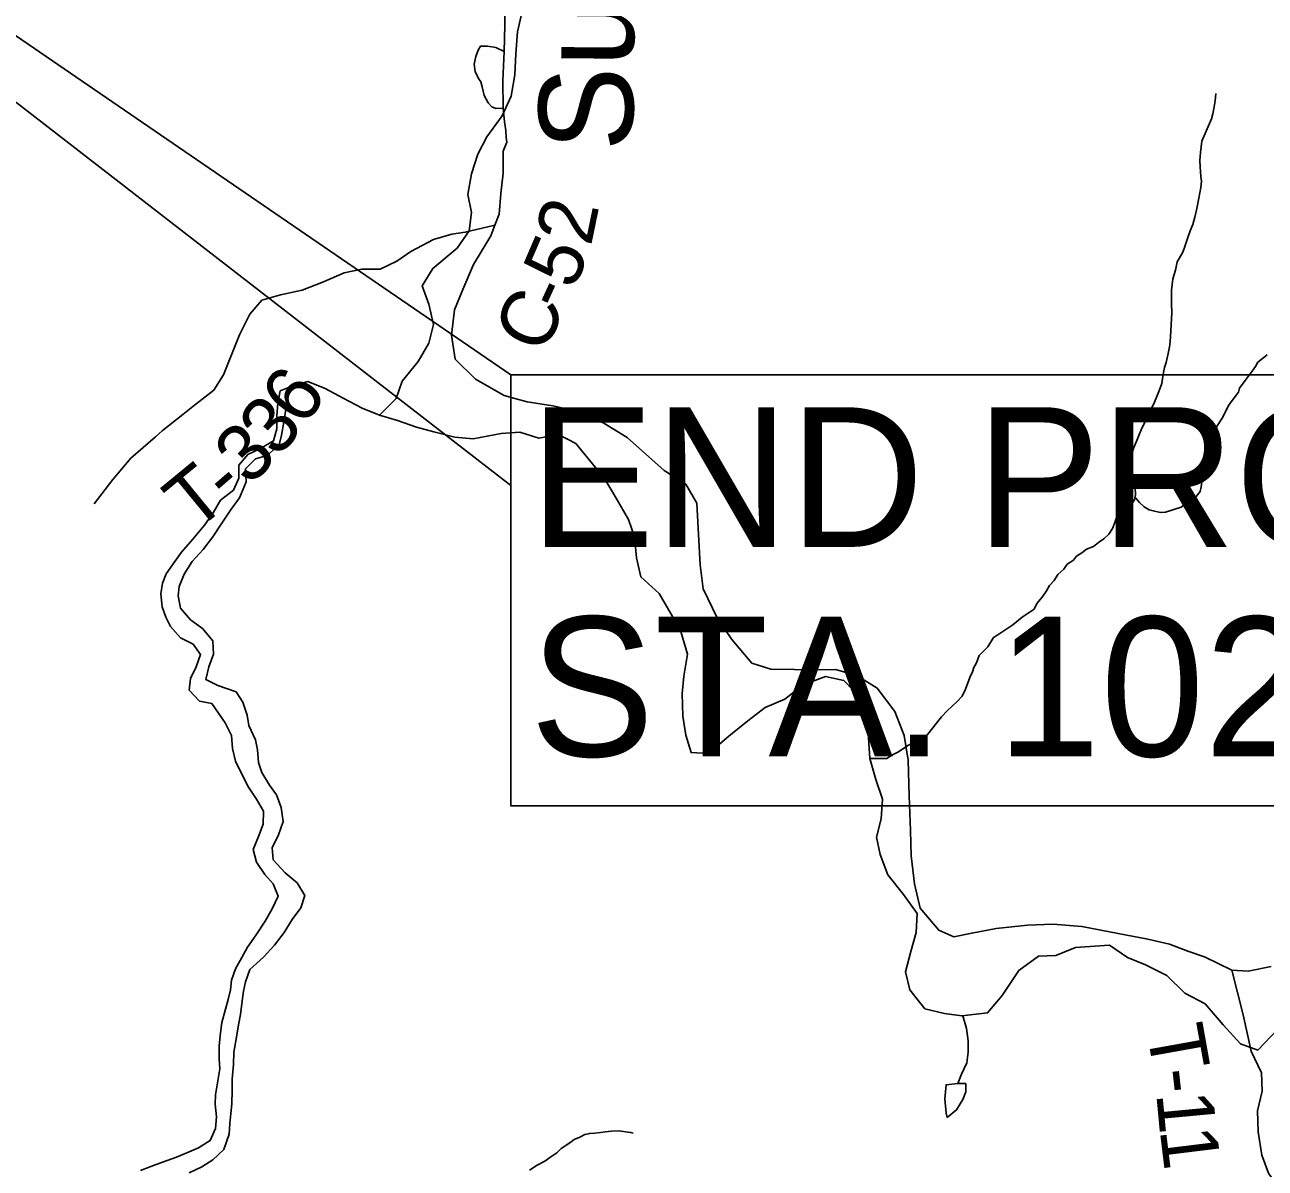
# Model space of a CAD drawing. Extents: x 0 to 34, y 0 to 22.
# Drawn here: x 5.45 to 6.694, y 15.248 to 16.395 of the extents above; entities that cross this region are included whole.
import ezdxf

# ---------------------------------------------------------------- set-up
doc = ezdxf.new("R2010")
doc.units = 0
for name, color, linetype in [('GM_X_County_Road', 7, 'Continuous'), ('GM_X_County_Road_Text', 7, 'Continuous'), ('GM_X_Major_River', 7, 'Continuous'), ('GM_X_Minor_Lake', 7, 'Continuous'), ('GM_X_Minor_River', 7, 'Continuous'), ('GM_X_Minor_River_Text', 7, 'Continuous'), ('GM_X_Township_Road', 7, 'Continuous'), ('GM_X_Township_Road_Text', 7, 'Continuous'), ('SH_Masking', 7, 'Continuous'), ('SH_Text', 7, 'Continuous')]:
    doc.layers.add(name, color=color, linetype=linetype)

msp = doc.modelspace()

# ---------------------------------------------------------------- linework, layer by layer
at = {"layer": 'GM_X_County_Road'}
for points in [[(5.8701, 16.8242), (5.891, 16.8023), (5.9225, 16.7742), (5.9468, 16.7506), (5.9631, 16.7309), (5.9729, 16.7149), (5.979, 16.697), (5.9767, 16.6834), (5.9672, 16.667), (5.9459, 16.6408), (5.9303, 16.6131), (5.9231, 16.59), (5.9158, 16.5319), (5.918, 16.4715), (5.9279, 16.4388), (5.9313, 16.4187), (5.9313, 16.3944), (5.9308, 16.3677), (5.9294, 16.3385), (5.9297, 16.311), (5.9312, 16.2975), (5.9323, 16.2885), (5.9328, 16.2817)], [(5.9328, 16.2817), (5.9333, 16.2768), (5.9296, 16.2679), (5.9296, 16.2459), (5.9273, 16.2254), (5.9258, 16.2049), (5.9215, 16.1937), (5.9174, 16.1829), (5.8999, 16.1544), (5.8893, 16.1293), (5.8809, 16.1088), (5.8778, 16.0834), (5.8816, 16.0595), (5.9021, 16.0393), (5.9309, 16.023), (5.9414, 16.02)], [(5.9414, 16.02), (5.9537, 16.0165), (5.9796, 16.0127), (6.0058, 16.0066), (6.0308, 15.9952), (6.054, 15.9808), (6.0912, 15.9477), (6.1128, 15.934), (6.1238, 15.9151), (6.1253, 15.89), (6.1272, 15.8532), (6.1302, 15.8292), (6.1442, 15.8), (6.159, 15.7783), (6.1791, 15.7548), (6.1981, 15.7487), (6.222, 15.7483), (6.2482, 15.7479), (6.263, 15.7483), (6.2843, 15.7422), (6.3048, 15.7297), (6.3226, 15.7061), (6.3317, 15.6822), (6.3359, 15.6575), (6.337, 15.6215), (6.3381, 15.5869), (6.3388, 15.5615), (6.3422, 15.5334), (6.3479, 15.5091), (6.3665, 15.487), (6.3817, 15.4802), (6.3995, 15.484), (6.4239, 15.4885), (6.4554, 15.4919), (6.4812, 15.4931), (6.5101, 15.4908), (6.5465, 15.4835), (6.5761, 15.4778), (6.5978, 15.4729), (6.6164, 15.466), (6.6331, 15.4603), (6.6604, 15.447), (6.6768, 15.4459), (6.6999, 15.4504)]]:
    msp.add_lwpolyline(points, dxfattribs=at)
at = {"layer": 'GM_X_Major_River'}
for points in [[(5.6465, 15.8929), (5.6564, 15.9079), (5.6655, 15.9204), (5.672, 15.9363), (5.6713, 15.9496), (5.6815, 15.9594), (5.6933, 15.9628), (5.7051, 15.9734), (5.7074, 15.9832), (5.7097, 15.9961), (5.712, 16.0094), (5.7139, 16.0196), (5.7162, 16.0317)], [(5.7162, 16.0317), (5.7063, 16.0276), (5.704, 16.0154), (5.7029, 16.0026), (5.7028, 15.9897), (5.6994, 15.9775), (5.6857, 15.9696), (5.6736, 15.964), (5.6648, 15.953), (5.6647, 15.9401), (5.6594, 15.9282), (5.6465, 15.9179)], [(5.7162, 16.0317), (5.734, 16.037), (5.7514, 16.0301), (5.7695, 16.0202), (5.7884, 16.0103), (5.8058, 16.0034), (5.8239, 15.998), (5.8428, 15.9912), (5.8602, 15.9866), (5.8814, 15.9812), (5.8996, 15.9796), (5.9276, 15.9848), (5.9465, 15.9863), (5.9654, 15.9802), (5.9851, 15.9839), (6.0025, 15.9748), (6.0312, 15.9398), (6.0432, 15.92), (6.0553, 15.8988), (6.0613, 15.8813), (6.0635, 15.8601), (6.0679, 15.8411), (6.0861, 15.8244), (6.0981, 15.8038), (6.1079, 15.7864), (6.1146, 15.7636), (6.1108, 15.7416), (6.1092, 15.7242), (6.1099, 15.7014), (6.1129, 15.6825), (6.1181, 15.665), (6.1355, 15.6642), (6.156, 15.6816), (6.175, 15.6967), (6.1924, 15.7103), (6.2121, 15.7186), (6.2304, 15.7329), (6.2531, 15.7412), (6.2712, 15.7374), (6.2916, 15.7161), (6.2984, 15.6978), (6.296, 15.6797), (6.2975, 15.6592), (6.3035, 15.6379), (6.3102, 15.6182), (6.3087, 15.5985), (6.3041, 15.5803), (6.3078, 15.5628), (6.3153, 15.5423), (6.3311, 15.5226), (6.3447, 15.5036), (6.3439, 15.4846), (6.3385, 15.4657), (6.3332, 15.4452), (6.3376, 15.427), (6.3527, 15.408), (6.3724, 15.4034), (6.3898, 15.4011), (6.4155, 15.404), (6.43, 15.4214), (6.4467, 15.4464), (6.4664, 15.4608), (6.4838, 15.4615), (6.5036, 15.4697), (6.5376, 15.4719), (6.5557, 15.4597), (6.5739, 15.4521), (6.5951, 15.4414), (6.6132, 15.4239), (6.6336, 15.4132), (6.6517, 15.392), (6.669, 15.373), (6.6864, 15.3668), (6.7062, 15.3873)], [(5.6465, 15.9179), (5.6389, 15.9054), (5.6302, 15.8929), (5.6185, 15.8789), (5.6072, 15.866), (5.6004, 15.8565), (5.592, 15.8443), (5.5883, 15.8349), (5.5864, 15.8242), (5.5879, 15.811), (5.5917, 15.8007), (5.5962, 15.7913), (5.6064, 15.7799), (5.6189, 15.7738), (5.6264, 15.7632), (5.6219, 15.7511), (5.6162, 15.7393), (5.6151, 15.7276), (5.6253, 15.7166), (5.6378, 15.7143)], [(5.6438, 15.7321), (5.6317, 15.7382), (5.6347, 15.7511), (5.6393, 15.7636), (5.6385, 15.7772), (5.6283, 15.7894), (5.6162, 15.7981), (5.6064, 15.8098), (5.6038, 15.822), (5.6049, 15.8315), (5.6098, 15.844), (5.6181, 15.8565), (5.6291, 15.8686), (5.6385, 15.8812), (5.6465, 15.8929)], [(5.6497, 15.2672), (5.6551, 15.2826), (5.6558, 15.2932), (5.6566, 15.3031), (5.6578, 15.3129), (5.6582, 15.3266), (5.6582, 15.3375), (5.6594, 15.3523), (5.6598, 15.3648), (5.6621, 15.3777), (5.6644, 15.3921), (5.6663, 15.4023), (5.6682, 15.416), (5.6694, 15.4258), (5.6713, 15.4353), (5.6759, 15.4474), (5.6896, 15.4599), (5.7006, 15.472), (5.7101, 15.4845), (5.7181, 15.4977), (5.7268, 15.5094), (5.731, 15.5219), (5.7231, 15.5345), (5.7113, 15.5443), (5.6992, 15.5576), (5.6981, 15.5694), (5.7046, 15.5826), (5.7092, 15.5959), (5.7073, 15.6099), (5.7024, 15.6228), (5.6956, 15.6323), (5.6877, 15.6452), (5.6843, 15.6551), (5.6836, 15.6676), (5.6813, 15.6778), (5.6746, 15.692), (5.673, 15.7025), (5.6689, 15.7157), (5.6619, 15.7259), (5.6438, 15.7321)], [(5.6378, 15.7143), (5.651, 15.6949), (5.6574, 15.682), (5.6585, 15.6691), (5.6615, 15.6563), (5.668, 15.6426), (5.6744, 15.6305), (5.6823, 15.6183), (5.6895, 15.6062), (5.6891, 15.5933), (5.6845, 15.5808), (5.6792, 15.5679), (5.6826, 15.555), (5.6909, 15.5429), (5.6992, 15.5334), (5.7041, 15.5212), (5.698, 15.5084), (5.6911, 15.4959), (5.682, 15.4823), (5.6733, 15.4698), (5.6676, 15.4596), (5.6615, 15.4482), (5.6573, 15.4368), (5.6565, 15.427), (5.6542, 15.4175), (5.6512, 15.4077), (5.6477, 15.3944), (5.6462, 15.3842), (5.645, 15.3709), (5.645, 15.358), (5.6457, 15.3478)], [(5.6457, 15.3478), (5.6414, 15.3218), (5.6411, 15.3124), (5.6422, 15.2999), (5.6414, 15.2881), (5.6361, 15.276), (5.6244, 15.2688), (5.6127, 15.2638), (5.6021, 15.2593), (5.5881, 15.2543), (5.5764, 15.2501), (5.5662, 15.246)], [(5.615, 15.2437), (5.6278, 15.2498), (5.6388, 15.2566), (5.6497, 15.2672)]]:
    msp.add_lwpolyline(points, dxfattribs=at)
at = {"layer": 'GM_X_Minor_Lake'}
for points in [[(6.3855, 15.3332), (6.3738, 15.332), (6.3727, 15.318), (6.3738, 15.3036), (6.3749, 15.2991)], [(6.3749, 15.2991), (6.3844, 15.3067), (6.3908, 15.3173), (6.3935, 15.3248), (6.3935, 15.3332), (6.3855, 15.3332)]]:
    msp.add_lwpolyline(points, dxfattribs=at)
at = {"layer": 'GM_X_Minor_River'}
for points in [[(5.9494, 16.411), (5.944, 16.3875), (5.9424, 16.3655), (5.9416, 16.3443), (5.9377, 16.3231), (5.9286, 16.3034), (5.9134, 16.2822), (5.9043, 16.2648), (5.8981, 16.2451), (5.8943, 16.2246), (5.898, 16.2064), (5.8957, 16.1882), (5.8835, 16.1708), (5.8592, 16.1504), (5.8486, 16.133), (5.8553, 16.1147), (5.8598, 16.0943), (5.8552, 16.0753), (5.8446, 16.0571), (5.8286, 16.0375), (5.8225, 16.02), (5.8058, 16.0034)], [(6.2975, 15.6592), (6.3143, 15.6591), (6.3209, 15.6631), (6.3262, 15.6657), (6.3354, 15.672), (6.3461, 15.6771), (6.3534, 15.6812), (6.3569, 15.6853), (6.363, 15.6928), (6.3692, 15.7007), (6.375, 15.707), (6.385, 15.7163), (6.3901, 15.7216), (6.3932, 15.7287), (6.3976, 15.7404), (6.4003, 15.7461), (6.4016, 15.7502), (6.4043, 15.7551), (6.4071, 15.7623), (6.4156, 15.7709), (6.4214, 15.7803), (6.4256, 15.7832), (6.4409, 15.7932), (6.4502, 15.8007), (6.4621, 15.8088), (6.4648, 15.8145), (6.4702, 15.8208), (6.4745, 15.8272), (6.4776, 15.8325), (6.4822, 15.8374), (6.4858, 15.8434), (6.4919, 15.849), (6.4954, 15.8538), (6.5015, 15.8579), (6.5047, 15.862), (6.51, 15.8654), (6.5146, 15.8691), (6.5215, 15.8716), (6.5265, 15.8757), (6.5319, 15.8794), (6.5369, 15.8839), (6.5407, 15.8895), (6.5431, 15.8956), (6.5443, 15.8997), (6.5474, 15.9042), (6.552, 15.9068), (6.5548, 15.9113), (6.5601, 15.9143), (6.5628, 15.9184), (6.5637, 15.9233), (6.5634, 15.9305), (6.5613, 15.9378), (6.5591, 15.9435), (6.5581, 15.9519), (6.5582, 15.9587), (6.5622, 15.9708), (6.565, 15.978), (6.567, 15.9829), (6.5702, 15.9904), (6.5729, 15.9953), (6.5776, 16.0062), (6.582, 16.0145), (6.5871, 16.027), (6.5903, 16.0349), (6.5907, 16.0398), (6.592, 16.0459), (6.5928, 16.0512), (6.5944, 16.0561), (6.5965, 16.0652), (6.5981, 16.0735), (6.599, 16.0818), (6.6002, 16.1061), (6.6, 16.1145), (6.5997, 16.1202), (6.5999, 16.1285), (6.6012, 16.1399), (6.604, 16.1486), (6.6057, 16.1569), (6.6108, 16.166), (6.6124, 16.1705), (6.6159, 16.1803), (6.6187, 16.1879), (6.6211, 16.1943), (6.6231, 16.2018), (6.6252, 16.2105), (6.6273, 16.2208), (6.6293, 16.2314), (6.6298, 16.2378), (6.6292, 16.2427), (6.6289, 16.2477), (6.6286, 16.2523), (6.6283, 16.2587), (6.6288, 16.2667), (6.6302, 16.2781), (6.6345, 16.2879), (6.64, 16.3003), (6.6412, 16.3052), (6.6425, 16.3124), (6.6437, 16.3185), (6.6442, 16.3257)], [(6.5636, 15.9203), (6.5677, 15.9157), (6.5726, 15.9114), (6.5774, 15.9083), (6.5816, 15.9074), (6.5888, 15.9058), (6.5937, 15.9061), (6.6097, 15.9111), (6.6158, 15.916), (6.6231, 15.92), (6.6285, 15.9268), (6.6297, 15.9313), (6.6306, 15.9381), (6.6315, 15.9438), (6.6316, 15.951), (6.6333, 15.9601), (6.6361, 15.9692), (6.6389, 15.9794), (6.6432, 15.9865), (6.6456, 15.9926), (6.6514, 16.0012), (6.6553, 16.0095), (6.6577, 16.014), (6.667, 16.0264), (6.6682, 16.0305), (6.6737, 16.038), (6.6806, 16.0474), (6.6841, 16.0519), (6.6865, 16.0564), (6.6957, 16.0639)], [(6.3906, 15.4012), (6.3942, 15.3885), (6.3961, 15.376), (6.3961, 15.3646), (6.3946, 15.354), (6.3893, 15.3426), (6.3855, 15.3332), (6.3863, 15.3332)], [(5.956, 15.2463), (5.964, 15.2515), (5.9716, 15.2555), (5.9774, 15.2596), (5.9835, 15.2637), (5.9878, 15.2682), (5.9966, 15.2737), (6.0008, 15.2771), (6.0065, 15.2796), (6.0115, 15.2822), (6.0165, 15.2832), (6.0218, 15.2835), (6.0275, 15.2842), (6.0324, 15.2849), (6.0385, 15.2855), (6.046, 15.2858), (6.0525, 15.2849), (6.0578, 15.2841), (6.0602, 15.2835)]]:
    msp.add_lwpolyline(points, dxfattribs=at)
at = {"layer": 'GM_X_Township_Road'}
for points in [[(5.9297, 16.311), (5.9225, 16.3106), (5.9185, 16.3124), (5.9148, 16.3163), (5.9108, 16.3239), (5.9087, 16.3325), (5.9075, 16.3373), (5.905, 16.3408), (5.9016, 16.3477), (5.9008, 16.3553), (5.9024, 16.3629), (5.9046, 16.3692), (5.907, 16.3731), (5.9142, 16.3731), (5.9225, 16.3719), (5.9308, 16.3677)], [(5.9215, 16.1937), (5.8917, 16.1866), (5.8782, 16.1848), (5.8599, 16.1793), (5.8373, 16.1675), (5.8231, 16.1577), (5.8065, 16.1498), (5.7882, 16.1498), (5.7703, 16.146), (5.7497, 16.1369), (5.7283, 16.1287), (5.7066, 16.1239), (5.6879, 16.1185), (5.6758, 16.1045), (5.6655, 16.0838), (5.6494, 16.0437), (5.6396, 16.0283), (5.6187, 16.0119), (5.6086, 16.004)], [(5.6086, 16.004), (5.5879, 15.9876), (5.5811, 15.9817), (5.5564, 15.9601), (5.5384, 15.9387), (5.5196, 15.9144)], [(6.703, 15.2346), (6.6971, 15.2435), (6.6903, 15.2613), (6.6869, 15.2849), (6.6861, 15.3058), (6.6907, 15.3255), (6.69, 15.3441), (6.6797, 15.3658), (6.6718, 15.4022), (6.6604, 15.447)]]:
    msp.add_lwpolyline(points, dxfattribs=at)
at = {"layer": 'SH_Masking'}
msp.add_lwpolyline([(5.9375, 16.0436), (7.4049, 16.0436), (7.4049, 15.6115), (5.9375, 15.6115)], close=True, dxfattribs=at)
at = {"layer": 'SH_Text'}
for points in [[(4.6965, 16.8937), (5.9375, 16.0436), (5.9375, 15.9329)], [(5.9375, 16.0436), (7.4049, 16.0436), (7.4049, 15.6115), (5.9375, 15.6115)]]:
    msp.add_lwpolyline(points, close=True, dxfattribs=at)

# ---------------------------------------------------------------- texts
at = {"layer": 'GM_X_County_Road_Text'}
for s, rotation, p in [('2', 78.3586, (6.0177, 16.1718)), ('5', 66.713, (6.0001, 16.1276)), ('-', 65.3944, (5.9898, 16.1051)), ('C', 65.1724, (5.9701, 16.0625))]:
    msp.add_text(s, height=0.0568, rotation=rotation, dxfattribs=at).set_placement(p)
at = {"layer": 'GM_X_Minor_River_Text'}
msp.add_text('Sugar', height=0.09469, rotation=89.4916, dxfattribs=at).set_placement((6.0598, 16.2678))
at = {"layer": 'GM_X_Township_Road_Text'}
for s, rotation, p in [('6', 54.4626, (5.7297, 15.9903)), ('3', 49.2722, (5.7034, 15.9594)), ('3', 44.6517, (5.6751, 15.9312)), ('T', 39.3855, (5.6204, 15.8851)), ('-', 40.8273, (5.6544, 15.9131)), ('T', 280.1672, (6.5746, 15.3871)), ('-', 276.3357, (6.582, 15.3463)), ('1', 275.3575, (6.5845, 15.3233)), ('1', 276.9768, (6.588, 15.2868))]:
    msp.add_text(s, height=0.0568, rotation=rotation, dxfattribs=at).set_placement(p)
at = {"layer": 'SH_Text'}
for s, p in [('END PROJECT', (5.9565, 15.8712)), ('STA. 102+34.91', (5.9565, 15.6612))]:
    msp.add_text(s, height=0.14, dxfattribs=at).set_placement(p)

doc.saveas('drawing.dxf')
